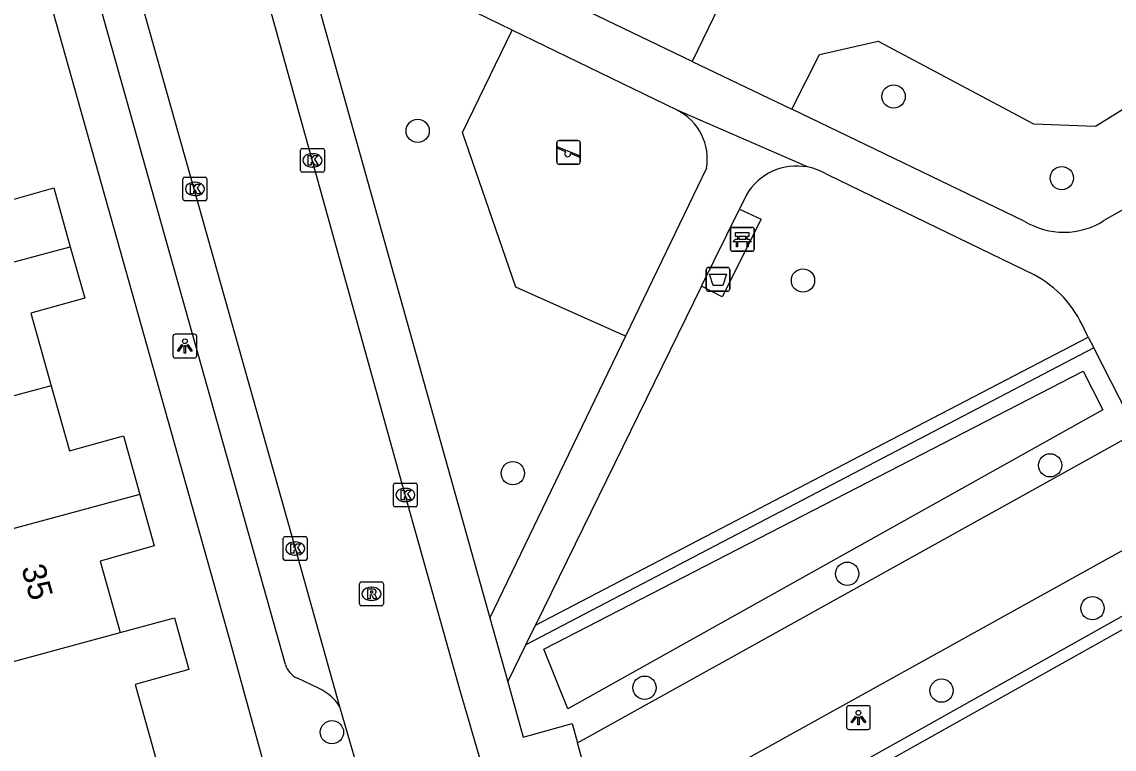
# Model space of a CAD drawing. Extents: x 159628 to 160723, y 388176 to 389416.
# Drawn here: x 160120.05 to 160165.93, y 388467.68 to 388498.23 of the extents above; entities that cross this region are included whole.
import ezdxf

# ---------------------------------------------------------------- set-up
doc = ezdxf.new("R2010")
doc.units = 0
for name, color, linetype in [('IMGEO_Afvalbak', 7, 'Continuous'), ('IMGEO_Bank', 7, 'Continuous'), ('IMGEO_Boom', 7, 'Continuous'), ('IMGEO_Groenvoorziening', 7, 'Continuous'), ('IMGEO_Haag', 7, 'Continuous'), ('IMGEO_Kolk', 7, 'Continuous'), ('IMGEO_Lichtpunt', 7, 'Continuous'), ('IMGEO_Pand', 7, 'Continuous'), ('IMGEO_Pand_nummerreeks', 7, 'Continuous'), ('IMGEO_Rijbaan_lokaal_open', 7, 'Continuous'), ('IMGEO_Rioolput', 7, 'Continuous'), ('IMGEO_Speelvoorziening', 7, 'Continuous'), ('IMGEO_Voetpad_halfverhard', 7, 'Continuous'), ('IMGEO_Voetpad_open', 7, 'Continuous'), ('IMGEO_Waterloop', 7, 'Continuous')]:
    doc.layers.add(name, color=color, linetype=linetype)

msp = doc.modelspace()

# ---------------------------------------------------------------- linework, layer by layer
at = {"layer": 'IMGEO_Afvalbak'}
for p, q in [((160148.795, 388487.013), (160148.795, 388487.813)), ((160148.795, 388487.813), (160148.795, 388487.013)), ((160148.895, 388487.913), (160149.685, 388487.913)), ((160149.685, 388487.913), (160148.895, 388487.913)), ((160149.785, 388487.813), (160149.785, 388487.013)), ((160149.785, 388487.013), (160149.785, 388487.813)), ((160149.685, 388486.913), (160148.895, 388486.913)), ((160148.895, 388486.913), (160149.685, 388486.913))]:
    msp.add_line(p, q, dxfattribs=at)
msp.add_lwpolyline([(160148.938, 388487.627), (160149.642, 388487.627), (160149.493, 388487.157), (160149.087, 388487.157), (160148.938, 388487.627)], dxfattribs=at)
for centre, start, end in [((160148.895, 388487.813), 90, 180), ((160148.895, 388487.813), 90, 180), ((160149.685, 388487.813), 0, 90), ((160149.685, 388487.813), 360, 90), ((160148.895, 388487.013), 180, 270), ((160148.895, 388487.013), 180, 270), ((160149.685, 388487.013), 270, 0), ((160149.685, 388487.013), 270, 0)]:
    msp.add_arc(centre, 0.1, start, end, dxfattribs=at)
at = {"layer": 'IMGEO_Bank'}
for p, q in [((160149.809, 388488.671), (160149.809, 388489.512)), ((160149.809, 388489.512), (160149.809, 388488.671)), ((160149.884, 388489.596), (160150.725, 388489.596)), ((160150.725, 388489.596), (160149.884, 388489.596)), ((160150.118, 388489.102), (160150.118, 388489.208)), ((160150.162, 388489.208), (160150.162, 388489.102)), ((160150.45, 388489.214), (160150.168, 388489.214)), ((160150.456, 388489.102), (160150.456, 388489.208)), ((160150.5, 388489.208), (160150.5, 388489.102)), ((160150.809, 388489.521), (160150.809, 388488.68)), ((160150.809, 388488.68), (160150.809, 388489.521)), ((160150.506, 388488.994), (160150.113, 388488.994)), ((160150.168, 388489.096), (160150.45, 388489.096)), ((160150.734, 388488.596), (160149.893, 388488.596)), ((160149.893, 388488.596), (160150.734, 388488.596))]:
    msp.add_line(p, q, dxfattribs=at)
for points in [[(160150.112, 388489.214), (160150.026, 388489.214), (160150.026, 388489.375), (160150.589, 388489.375), (160150.589, 388489.214), (160150.506, 388489.214)], [(160150.056, 388488.994), (160149.914, 388488.994), (160150.026, 388489.096), (160150.112, 388489.096)], [(160150.106, 388488.987), (160150.106, 388488.78), (160150.063, 388488.78), (160150.063, 388488.987)], [(160150.506, 388489.096), (160150.589, 388489.096), (160150.701, 388488.994), (160150.562, 388488.994)], [(160150.556, 388488.987), (160150.556, 388488.78), (160150.512, 388488.78), (160150.512, 388488.987)]]:
    msp.add_lwpolyline(points, dxfattribs=at)
for centre, radius, start, end in [((160149.887, 388489.518), 0.0779, 92.4484, 184.2845), ((160149.887, 388489.518), 0.0779, 92.4484, 184.2845), ((160150.111, 388489.207), 0.00671, 2.8957, 87.1043), ((160150.168, 388489.207), 0.00671, 92.8957, 177.1043), ((160150.45, 388489.207), 0.00671, 2.8957, 87.1043), ((160150.507, 388489.207), 0.00671, 92.8957, 177.1043), ((160150.731, 388489.518), 0.0779, 2.4484, 94.2845), ((160150.731, 388489.518), 0.0779, 2.4484, 94.2845), ((160150.056, 388488.987), 0.00671, 2.8957, 87.1043), ((160150.113, 388488.987), 0.00671, 92.8957, 177.1043), ((160150.111, 388489.103), 0.00671, 272.8957, 357.1043), ((160150.168, 388489.103), 0.00671, 182.8957, 267.1043), ((160150.45, 388489.103), 0.00671, 272.8957, 357.1043), ((160150.507, 388489.103), 0.00671, 182.8957, 267.1043), ((160150.505, 388488.987), 0.00671, 2.8957, 87.1043), ((160150.562, 388488.987), 0.00671, 92.8957, 177.1043), ((160149.887, 388488.674), 0.0779, 182.4484, 274.2845), ((160149.887, 388488.674), 0.0779, 182.4484, 274.2845), ((160150.731, 388488.674), 0.0779, 272.4484, 4.2845), ((160150.731, 388488.674), 0.0779, 272.4484, 4.2845)]:
    msp.add_arc(centre, radius, start, end, dxfattribs=at)
at = {"layer": 'IMGEO_Boom'}
for centre in [(160156.664, 388495.093), (160136.675, 388493.649), (160163.728, 388491.667), (160152.858, 388487.366), (160163.237, 388479.604), (160140.672, 388479.271), (160154.716, 388475.051), (160165.017, 388473.603), (160146.204, 388470.264), (160158.679, 388470.142), (160133.074, 388468.394)]:
    msp.add_circle(centre, 0.489, dxfattribs=at)
at = {"layer": 'IMGEO_Groenvoorziening'}
for points in [[(160152.383, 388494.557), (160153.556, 388496.852), (160156.02, 388497.416), (160162.543, 388493.95), (160165.142, 388493.842), (160175.064, 388500), (160177.11, 388501.27), (160178.44, 388505.363), (160181.909, 388508.629), (160198.334, 388518.23), (160202.489, 388519.687), (160206.028, 388519.532), (160210.488, 388518.84), (160212.982, 388520.976), (160216.139, 388531.214), (160220.785, 388533.458)], [(160143.857, 388498.653), (160144.502, 388500), (160145.205, 388501.466), (160148.256, 388500), (160149.567, 388499.37), (160148.203, 388496.565)], [(160145.405, 388485.027), (160140.797, 388487.087), (160138.562, 388493.582), (160140.637, 388497.878)]]:
    msp.add_lwpolyline(points, dxfattribs=at)
at = {"layer": 'IMGEO_Haag'}
for points in [[(160141.622, 388472.885), (160155.907, 388480.332), (160164.84, 388484.987)], [(160165.069, 388484.539), (160156.509, 388480.063), (160141.221, 388472.068)], [(160145.181, 388461.454), (160170.636, 388475.72)], [(160170.867, 388475.276), (160145.318, 388460.958)]]:
    msp.add_lwpolyline(points, dxfattribs=at)
at = {"layer": 'IMGEO_Kolk'}
for p, q in [((160131.756, 388491.986), (160131.756, 388492.838)), ((160131.831, 388492.912), (160132.683, 388492.912)), ((160132.757, 388492.838), (160132.757, 388491.986)), ((160132.244, 388492.692), (160132.269, 388492.692)), ((160132.683, 388491.912), (160131.831, 388491.912)), ((160132.267, 388492.132), (160132.242, 388492.132)), ((160126.819, 388490.786), (160126.819, 388491.638)), ((160126.894, 388491.712), (160127.746, 388491.712)), ((160127.307, 388491.492), (160127.332, 388491.492)), ((160127.82, 388491.638), (160127.82, 388490.786)), ((160127.746, 388490.712), (160126.894, 388490.712)), ((160127.33, 388490.932), (160127.305, 388490.932)), ((160135.657, 388477.932), (160135.657, 388478.784)), ((160135.732, 388478.858), (160136.584, 388478.858)), ((160136.145, 388478.638), (160136.17, 388478.638)), ((160136.658, 388478.784), (160136.658, 388477.932)), ((160136.584, 388477.858), (160135.732, 388477.858)), ((160136.168, 388478.078), (160136.143, 388478.078)), ((160131.032, 388475.683), (160131.032, 388476.535)), ((160131.107, 388476.609), (160131.959, 388476.609)), ((160131.52, 388476.389), (160131.545, 388476.389)), ((160132.033, 388476.535), (160132.033, 388475.683)), ((160131.959, 388475.609), (160131.107, 388475.609)), ((160131.543, 388475.829), (160131.518, 388475.829))]:
    msp.add_line(p, q, dxfattribs=at)
for points in [[(160131.756, 388491.986), (160131.756, 388492.838)], [(160131.831, 388492.912), (160132.683, 388492.912)], [(160132.757, 388492.838), (160132.757, 388491.986)], [(160132.077, 388492.612), (160132.2, 388492.612), (160132.2, 388492.461), (160132.33, 388492.612), (160132.494, 388492.612), (160132.348, 388492.461), (160132.501, 388492.212), (160132.349, 388492.212), (160132.264, 388492.376), (160132.2, 388492.309), (160132.2, 388492.212), (160132.077, 388492.212), (160132.077, 388492.612)], [(160132.683, 388491.912), (160131.831, 388491.912)], [(160126.819, 388490.786), (160126.819, 388491.638)], [(160126.894, 388491.712), (160127.746, 388491.712)], [(160127.82, 388491.638), (160127.82, 388490.786)], [(160127.14, 388491.412), (160127.263, 388491.412), (160127.263, 388491.261), (160127.393, 388491.412), (160127.557, 388491.412), (160127.411, 388491.261), (160127.564, 388491.012), (160127.412, 388491.012), (160127.327, 388491.176), (160127.263, 388491.109), (160127.263, 388491.012), (160127.14, 388491.012), (160127.14, 388491.412)], [(160127.746, 388490.712), (160126.894, 388490.712)], [(160135.657, 388477.932), (160135.657, 388478.784)], [(160135.732, 388478.858), (160136.584, 388478.858)], [(160136.658, 388478.784), (160136.658, 388477.932)], [(160135.978, 388478.558), (160136.101, 388478.558), (160136.101, 388478.407), (160136.231, 388478.558), (160136.395, 388478.558), (160136.249, 388478.407), (160136.402, 388478.158), (160136.25, 388478.158), (160136.165, 388478.322), (160136.101, 388478.255), (160136.101, 388478.158), (160135.978, 388478.158), (160135.978, 388478.558)], [(160136.584, 388477.858), (160135.732, 388477.858)], [(160131.032, 388475.683), (160131.032, 388476.535)], [(160131.107, 388476.609), (160131.959, 388476.609)], [(160131.353, 388476.309), (160131.476, 388476.309), (160131.476, 388476.158), (160131.606, 388476.309), (160131.77, 388476.309), (160131.624, 388476.158), (160131.777, 388475.909), (160131.625, 388475.909), (160131.54, 388476.073), (160131.476, 388476.006), (160131.476, 388475.909), (160131.353, 388475.909), (160131.353, 388476.309)], [(160132.033, 388476.535), (160132.033, 388475.683)], [(160131.959, 388475.609), (160131.107, 388475.609)]]:
    msp.add_lwpolyline(points, dxfattribs=at)
for centre, start, end in [((160131.833, 388492.836), 91.552, 178.448), ((160131.833, 388492.836), 91.552, 178.448), ((160132.681, 388492.836), 1.552, 88.448), ((160132.681, 388492.836), 1.552, 88.448), ((160131.833, 388491.988), 181.552, 268.448), ((160131.833, 388491.988), 181.552, 268.448), ((160132.681, 388491.988), 271.552, 358.448), ((160132.681, 388491.988), 271.552, 358.448), ((160126.896, 388491.636), 91.552, 178.448), ((160126.896, 388491.636), 91.552, 178.448), ((160127.744, 388491.636), 1.552, 88.448), ((160127.744, 388491.636), 1.552, 88.448), ((160126.896, 388490.788), 181.552, 268.448), ((160126.896, 388490.788), 181.552, 268.448), ((160127.744, 388490.788), 271.552, 358.448), ((160127.744, 388490.788), 271.552, 358.448), ((160135.734, 388478.782), 91.552, 178.448), ((160135.734, 388478.782), 91.552, 178.448), ((160136.582, 388478.782), 1.552, 88.448), ((160136.582, 388478.782), 1.552, 88.448), ((160135.734, 388477.934), 181.552, 268.448), ((160135.734, 388477.934), 181.552, 268.448), ((160136.582, 388477.934), 271.552, 358.448), ((160136.582, 388477.934), 271.552, 358.448), ((160131.109, 388476.533), 91.552, 178.448), ((160131.109, 388476.533), 91.552, 178.448), ((160131.957, 388476.533), 1.552, 88.448), ((160131.957, 388476.533), 1.552, 88.448), ((160131.109, 388475.685), 181.552, 268.448), ((160131.109, 388475.685), 181.552, 268.448), ((160131.957, 388475.685), 271.552, 358.448), ((160131.957, 388475.685), 271.552, 358.448)]:
    msp.add_arc(centre, 0.0765, start, end, dxfattribs=at)
for centre, major_axis, ratio, start_param, end_param in [((160132.243, 388492.412), (-0.387, 0.002), 0.722429, 4.712389, 7.853982), ((160132.268, 388492.412), (-0.39, 0.002), 0.717154, 1.570796, 4.712389), ((160127.306, 388491.212), (-0.387, 0.002), 0.722429, 4.712389, 7.853982), ((160127.331, 388491.212), (-0.39, 0.002), 0.717154, 1.570796, 4.712389), ((160136.144, 388478.358), (-0.387, 0.002), 0.722429, 4.712389, 7.853982), ((160136.169, 388478.358), (-0.39, 0.002), 0.717154, 1.570796, 4.712389), ((160131.519, 388476.109), (-0.387, 0.002), 0.722429, 4.712389, 7.853982), ((160131.544, 388476.109), (-0.39, 0.002), 0.717154, 1.570796, 4.712389)]:
    msp.add_ellipse(centre, major_axis=major_axis, ratio=ratio, start_param=start_param, end_param=end_param, dxfattribs=at)
at = {"layer": 'IMGEO_Lichtpunt'}
for p, q in [((160127.301, 388485.112), (160126.493, 388485.112)), ((160127.301, 388485.112), (160126.493, 388485.112)), ((160126.399, 388485.017), (160126.399, 388484.21)), ((160126.399, 388485.017), (160126.399, 388484.21)), ((160127.395, 388484.21), (160127.395, 388485.017)), ((160127.395, 388484.21), (160127.395, 388485.017)), ((160126.493, 388484.116), (160127.301, 388484.116)), ((160126.493, 388484.116), (160127.301, 388484.116)), ((160155.592, 388469.507), (160154.784, 388469.507)), ((160155.592, 388469.507), (160154.784, 388469.507)), ((160154.69, 388469.412), (160154.69, 388468.605)), ((160154.69, 388469.412), (160154.69, 388468.605)), ((160155.686, 388468.605), (160155.686, 388469.412)), ((160155.686, 388468.605), (160155.686, 388469.412)), ((160154.784, 388468.511), (160155.592, 388468.511)), ((160154.784, 388468.511), (160155.592, 388468.511))]:
    msp.add_line(p, q, dxfattribs=at)
for points in [[(160126.773, 388484.681), (160126.812, 388484.653), (160126.624, 388484.391), (160126.586, 388484.418), (160126.773, 388484.681)], [(160126.875, 388484.633), (160126.922, 388484.633), (160126.922, 388484.311), (160126.875, 388484.311), (160126.875, 388484.633)], [(160126.985, 388484.653), (160127.023, 388484.68), (160127.21, 388484.418), (160127.171, 388484.39), (160126.985, 388484.653)], [(160155.064, 388469.076), (160155.103, 388469.048), (160154.915, 388468.786), (160154.877, 388468.813), (160155.064, 388469.076)], [(160155.166, 388469.028), (160155.213, 388469.028), (160155.213, 388468.706), (160155.166, 388468.706), (160155.166, 388469.028)], [(160155.276, 388469.048), (160155.314, 388469.075), (160155.501, 388468.813), (160155.462, 388468.785), (160155.276, 388469.048)]]:
    msp.add_lwpolyline(points, dxfattribs=at)
for centre in [(160126.898, 388484.815), (160155.189, 388469.21)]:
    msp.add_circle(centre, 0.0994, dxfattribs=at)
for centre, start, end in [((160126.493, 388485.017), 90, 180), ((160126.493, 388485.017), 90, 180), ((160127.301, 388485.017), 0, 90), ((160127.301, 388485.017), 0, 90), ((160126.493, 388484.21), 180, 270), ((160126.493, 388484.21), 180, 270), ((160127.301, 388484.21), 270, 0), ((160127.301, 388484.21), 270, 360), ((160154.784, 388469.412), 90, 180), ((160154.784, 388469.412), 90, 180), ((160155.592, 388469.412), 0, 90), ((160155.592, 388469.412), 0, 90), ((160154.784, 388468.605), 180, 270), ((160154.784, 388468.605), 180, 270), ((160155.592, 388468.605), 270, 0), ((160155.592, 388468.605), 270, 360)]:
    msp.add_arc(centre, 0.0946, start, end, dxfattribs=at)
at = {"layer": 'IMGEO_Pand'}
for points in [[(160117.167, 388492.996), (160118.369, 388493.328), (160119.129, 388490.62), (160121.391, 388491.255), (160122.085, 388488.785)], [(160108.438, 388485.103), (160110.987, 388485.817), (160122.085, 388488.785)], [(160122.085, 388488.785), (160122.692, 388486.624), (160120.43, 388485.989), (160121.287, 388482.94)], [(160121.287, 388482.94), (160112.457, 388480.571)], [(160121.287, 388482.94), (160122.053, 388480.213), (160124.315, 388480.848), (160125.007, 388478.383)], [(160125.007, 388478.383), (160113.91, 388475.385)], [(160125.007, 388478.383), (160125.615, 388476.217), (160123.343, 388475.579), (160124.184, 388472.586)], [(160124.184, 388472.586), (160126.461, 388473.205), (160127.069, 388471.036), (160124.807, 388470.402), (160126.452, 388464.539), (160116.486, 388459.468), (160114.4, 388466.915), (160113.11, 388466.545), (160112.321, 388469.361)], [(160112.321, 388469.361), (160124.184, 388472.586)]]:
    msp.add_lwpolyline(points, dxfattribs=at)
at = {"layer": 'IMGEO_Rijbaan_lokaal_open'}
for points in [[(160133.41, 388469.46), (160131.543, 388476.115), (160121.847, 388510.533)], [(160139.386, 388466.972), (160138.44, 388470.191), (160136.156, 388478.361), (160130.149, 388500), (160127.356, 388510.063), (160127.238, 388510.351)], [(160143.387, 388467.946), (160166.882, 388480.998)], [(160169.54, 388477.832), (160144.491, 388463.944)], [(160134.433, 388465.953), (160133.41, 388469.46)], [(160144.491, 388463.944), (160143.387, 388467.946)]]:
    msp.add_lwpolyline(points, dxfattribs=at)
at = {"layer": 'IMGEO_Rioolput'}
for p, q in [((160134.234, 388473.781), (160134.234, 388474.633)), ((160134.309, 388474.707), (160135.161, 388474.707)), ((160134.722, 388474.487), (160134.747, 388474.487)), ((160135.235, 388474.633), (160135.235, 388473.781)), ((160135.161, 388473.707), (160134.309, 388473.707)), ((160134.745, 388473.927), (160134.72, 388473.927))]:
    msp.add_line(p, q, dxfattribs=at)
for points in [[(160134.234, 388473.781), (160134.234, 388474.633)], [(160134.309, 388474.707), (160135.161, 388474.707)], [(160135.235, 388474.633), (160135.235, 388473.781)], [(160134.823, 388474.405), (160134.571, 388474.407), (160134.571, 388474.007)], [(160134.571, 388474.007), (160134.695, 388474.007), (160134.695, 388474.169), (160134.706, 388474.169)], [(160134.749, 388474.326), (160134.695, 388474.326), (160134.695, 388474.245)], [(160134.695, 388474.245), (160134.747, 388474.245)], [(160134.753, 388474.14), (160134.824, 388474.007), (160134.964, 388474.007), (160134.899, 388474.133)], [(160135.161, 388473.707), (160134.309, 388473.707)]]:
    msp.add_lwpolyline(points, dxfattribs=at)
for centre, radius, start, end in [((160134.311, 388474.631), 0.0765, 91.552, 178.448), ((160134.311, 388474.631), 0.0765, 91.552, 178.448), ((160135.159, 388474.631), 0.0765, 1.552, 88.448), ((160135.159, 388474.631), 0.0765, 1.552, 88.448), ((160134.705, 388474.116), 0.0533, 26.0293, 88.6989), ((160134.731, 388474.434), 0.19, 274.7715, 282.9687), ((160134.755, 388474.23), 0.0964, 77.0061, 93.1865), ((160134.769, 388474.287), 0.0378, 276.6634, 79.6772), ((160134.822, 388474.295), 0.109, 350.3612, 89.416), ((160134.82, 388474.295), 0.112, 277.5842, 350.9817), ((160134.804, 388474.08), 0.108, 29.5134, 73.7905), ((160134.311, 388473.783), 0.0765, 181.552, 268.448), ((160134.311, 388473.783), 0.0765, 181.552, 268.448), ((160135.159, 388473.783), 0.0765, 271.552, 358.448), ((160135.159, 388473.783), 0.0765, 271.552, 358.448)]:
    msp.add_arc(centre, radius, start, end, dxfattribs=at)
for centre, major_axis, ratio, start_param, end_param in [((160134.721, 388474.207), (-0.387, 0.002), 0.722429, 4.712389, 7.853982), ((160134.746, 388474.207), (-0.39, 0.002), 0.717154, 1.570796, 4.712389)]:
    msp.add_ellipse(centre, major_axis=major_axis, ratio=ratio, start_param=start_param, end_param=end_param, dxfattribs=at)
at = {"layer": 'IMGEO_Speelvoorziening'}
for p, q in [((160142.514, 388492.346), (160142.514, 388493.146)), ((160142.514, 388493.146), (160142.514, 388492.346)), ((160142.897, 388492.774), (160142.558, 388492.911)), ((160142.583, 388492.971), (160143.459, 388492.618)), ((160142.614, 388493.246), (160143.404, 388493.246)), ((160143.404, 388493.246), (160142.614, 388493.246)), ((160143.504, 388493.146), (160143.504, 388492.346)), ((160143.504, 388492.346), (160143.504, 388493.146)), ((160143.435, 388492.558), (160143.095, 388492.695)), ((160143.404, 388492.246), (160142.614, 388492.246)), ((160142.614, 388492.246), (160143.404, 388492.246))]:
    msp.add_line(p, q, dxfattribs=at)
for centre, radius, start, end in [((160142.614, 388493.146), 0.1, 90, 180), ((160142.614, 388493.146), 0.1, 90, 180), ((160142.571, 388492.941), 0.0327, 68.078, 248.078), ((160143.404, 388493.146), 0.1, 0, 90), ((160143.404, 388493.146), 0.1, 360, 90), ((160142.976, 388492.684), 0.12, 130.9928, 5.1632), ((160143.447, 388492.588), 0.0327, 248.078, 68.078), ((160142.614, 388492.346), 0.1, 180, 270), ((160142.614, 388492.346), 0.1, 180, 270), ((160143.404, 388492.346), 0.1, 270, 0), ((160143.404, 388492.346), 0.1, 270, 0)]:
    msp.add_arc(centre, radius, start, end, dxfattribs=at)
at = {"layer": 'IMGEO_Voetpad_halfverhard'}
for points in [[(160140.637, 388497.878), (160139.091, 388498.628)], [(160148.203, 388496.565), (160143.857, 388498.653)], [(160147.574, 388494.513), (160140.637, 388497.878)], [(160179.608, 388497.843), (160165.497, 388489.879)], [(160148.203, 388496.565), (160152.383, 388494.557)], [(160162.152, 388489.864), (160152.383, 388494.557)], [(160162.561, 388487.6), (160153.923, 388491.789)], [(160164.84, 388484.987), (160164.664, 388485.331)], [(160164.84, 388484.987), (160165.069, 388484.539)], [(160166.882, 388480.998), (160165.069, 388484.539)]]:
    msp.add_lwpolyline(points, dxfattribs=at)
for centre, radius, start, end in [((160152.596, 388489.697), 2.477, 57.6054, 79.624), ((160163.813, 388492.542), 3.151, 238.1987, 302.3152), ((160160.43, 388483.516), 4.606, 23.2034, 62.4478)]:
    msp.add_arc(centre, radius, start, end, dxfattribs=at)
at = {"layer": 'IMGEO_Voetpad_open'}
for points in [[(160130.611, 388465.651), (160128.765, 388472.373), (160120.983, 388500), (160116.838, 388514.716)], [(160128.841, 388512.015), (160132.204, 388500), (160139.703, 388473.203)], [(160131.118, 388471.243), (160123.03, 388500), (160120.814, 388507.878)], [(160153.042, 388492.134), (160147.574, 388494.513)], [(160148.805, 388492.077), (160145.405, 388485.027)], [(160150.483, 388490.966), (160150.189, 388490.366)], [(160150.189, 388490.366), (160151.105, 388489.946), (160149.47, 388486.685), (160148.602, 388487.127)], [(160148.602, 388487.127), (160150.189, 388490.366)], [(160148.602, 388487.127), (160141.622, 388472.885)], [(160145.405, 388485.027), (160139.703, 388473.203)], [(160139.703, 388473.203), (160140.457, 388470.509)], [(160141.221, 388472.068), (160141.622, 388472.885)], [(160140.457, 388470.509), (160141.221, 388472.068)], [(160132.51, 388470.241), (160131.621, 388470.668)], [(160140.457, 388470.509), (160140.57, 388470.105), (160141.107, 388468.188), (160143.161, 388468.763), (160143.387, 388467.946)]]:
    msp.add_lwpolyline(points, dxfattribs=at)
for centre, radius, start, end in [((160146.559, 388492.471), 2.28, 350.0478, 63.5704), ((160152.602, 388489.71), 2.463, 79.712, 149.3546), ((160131.978, 388471.487), 0.894, 195.8749, 246.4829), ((160131.671, 388468.365), 2.056, 32.2008, 65.8978)]:
    msp.add_arc(centre, radius, start, end, dxfattribs=at)
at = {"layer": 'IMGEO_Waterloop'}
msp.add_lwpolyline([(160141.977, 388471.877), (160164.62, 388483.563), (160165.445, 388481.928), (160142.982, 388469.378), (160141.977, 388471.877)], dxfattribs=at)

# ---------------------------------------------------------------- texts
at = {"layer": 'IMGEO_Pand_nummerreeks'}
msp.add_text('35', height=1, rotation=285.6301, dxfattribs=at).set_placement((160120.02, 388475.295))

doc.saveas('drawing.dxf')
